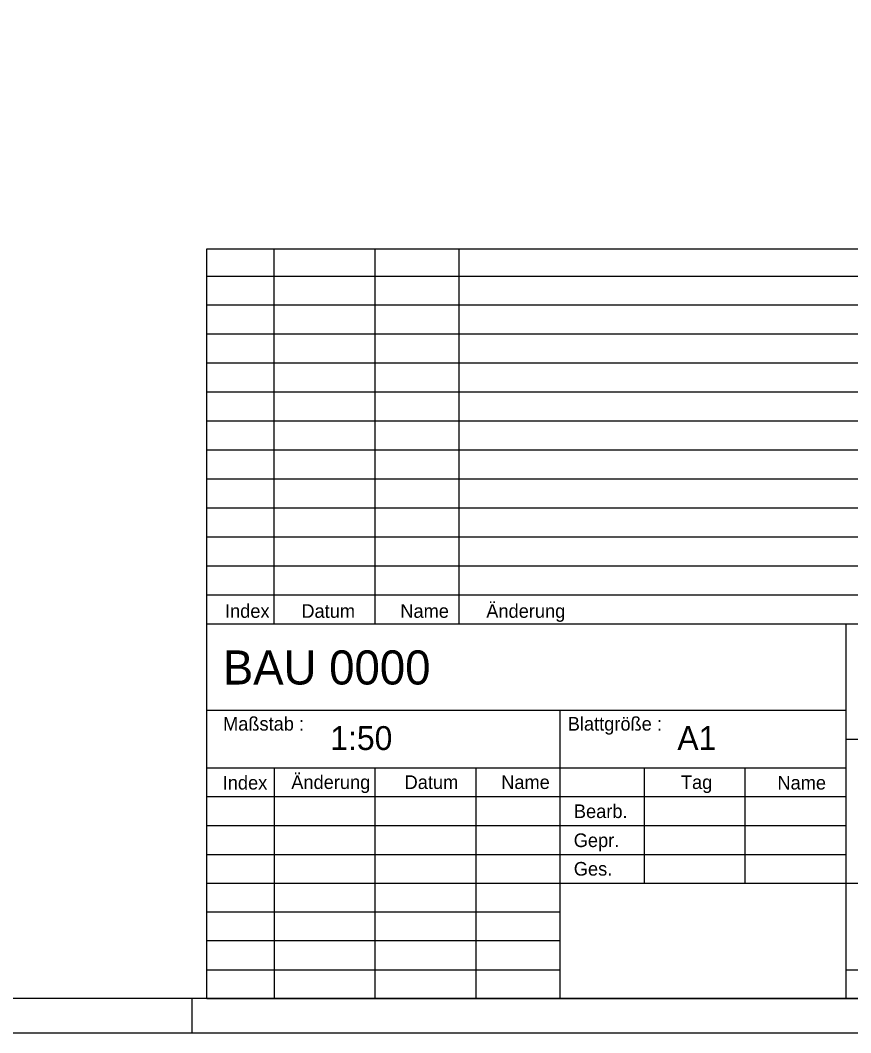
# Model space of a CAD drawing. Extents: x 0 to 42.1, y 0 to 29.7.
# Drawn here: x 31.54 to 37.63, y 0 to 7.43 of the extents above; entities that cross this region are included whole.
import ezdxf

# ---------------------------------------------------------------- set-up
doc = ezdxf.new("R2010")
doc.units = 0
doc.layers.add('90_Plankopf', color=7, linetype='Continuous')

msp = doc.modelspace()

# ---------------------------------------------------------------- linework, layer by layer
at = {"layer": '90_Plankopf'}
for p, q in [((32.906, 2.9995), (32.906, 5.749)), ((32.906, 5.749), (41.8, 5.749)), ((33.4001, 2.9995), (33.4001, 5.749)), ((34.1413, 2.9995), (34.1413, 5.749)), ((34.759, 2.9995), (34.759, 5.749)), ((32.906, 5.5495), (41.8, 5.5495)), ((32.906, 5.337), (41.8, 5.337)), ((32.906, 5.1245), (41.8, 5.1245)), ((32.906, 4.912), (41.8, 4.912)), ((32.906, 4.6995), (41.8, 4.6995)), ((32.906, 4.487), (41.8, 4.487)), ((32.906, 4.2745), (41.8, 4.2745)), ((32.906, 4.062), (41.8, 4.062)), ((32.906, 3.8495), (41.8, 3.8495)), ((32.906, 3.637), (41.8, 3.637)), ((32.906, 3.4245), (41.8, 3.4245)), ((32.906, 3.212), (41.8, 3.212)), ((32.906, 2.9995), (41.8, 2.9995)), ((32.906, 0.25), (32.906, 2.9995)), ((32.906, 2.9995), (41.8, 2.9995)), ((37.6001, 0.25), (37.6001, 2.9995)), ((32.906, 2.365), (37.6001, 2.365)), ((35.5001, 0.25), (35.5001, 2.365)), ((37.6001, 2.1535), (41.8, 2.1535)), ((32.906, 1.9435), (37.6001, 1.9435)), ((33.4001, 1.942), (33.4001, 0.25)), ((34.1413, 0.25), (34.1413, 1.942)), ((34.8825, 0.25), (34.8825, 1.942)), ((36.1177, 1.942), (36.1177, 1.096)), ((36.8589, 1.096), (36.8589, 1.942)), ((32.906, 1.7315), (37.6001, 1.7315)), ((32.906, 1.519), (37.6001, 1.519)), ((32.906, 1.3075), (37.6001, 1.3075)), ((32.906, 1.096), (37.6001, 1.096)), ((32.906, 1.096), (37.6001, 1.096)), ((35.5001, 1.096), (37.6001, 1.096)), ((37.6001, 1.096), (41.8, 1.096)), ((35.5001, 0.8845), (32.906, 0.8845)), ((35.5001, 0.673), (32.906, 0.673)), ((32.906, 0.4615), (35.5001, 0.4615)), ((37.6001, 0.4615), (41.8, 0.4615)), ((32.8, 0), (32.8, 0.25)), ((41.8, 0.25), (32.906, 0.25)), ((32.906, 0.25), (35.5001, 0.25)), ((33.49, 0.25), (41.8, 0.25)), ((33.49, 0.25), (41.8, 0.25))]:
    msp.add_line(p, q, dxfattribs=at)
for points in [[(0, 0), (42.05, 0), (42.05, 29.7), (0, 29.7)], [(1.25, 29.45), (41.8, 29.45), (41.8, 0.25), (1.25, 0.25)]]:
    msp.add_lwpolyline(points, close=True, dxfattribs=at)

# ---------------------------------------------------------------- texts
for s, height, p in [('Index', 0.1, (33.0402, 3.0428)), ('Datum', 0.1, (33.6007, 3.0428)), ('Name', 0.1, (34.3269, 3.0428)), ('Änderung', 0.1, (34.9579, 3.0428)), ('BAU 0000      ', 0.25, (33.0245, 2.5538)), ('Maßstab :', 0.1, (33.0258, 2.2158)), ('Blattgröße :', 0.099995, (35.5558, 2.2158)), ('1:50     ', 0.175, (33.8131, 2.0734)), ('A1       ', 0.175, (36.36, 2.0734)), ('Index', 0.1, (33.0235, 1.7837)), ('Änderung', 0.1, (33.5267, 1.7875)), ('Datum', 0.1, (34.3584, 1.7875)), ('Name', 0.1, (35.0674, 1.7875)), ('Tag', 0.1, (36.3862, 1.7875)), ('Name', 0.1, (37.0946, 1.7837)), ('Bearb.', 0.1, (35.6007, 1.5745)), ('Gepr.', 0.1, (35.5995, 1.3615)), ('Ges.', 0.1, (35.6002, 1.1523))]:
    msp.add_text(s, height=height, dxfattribs=at).set_placement(p)

doc.saveas('drawing.dxf')
